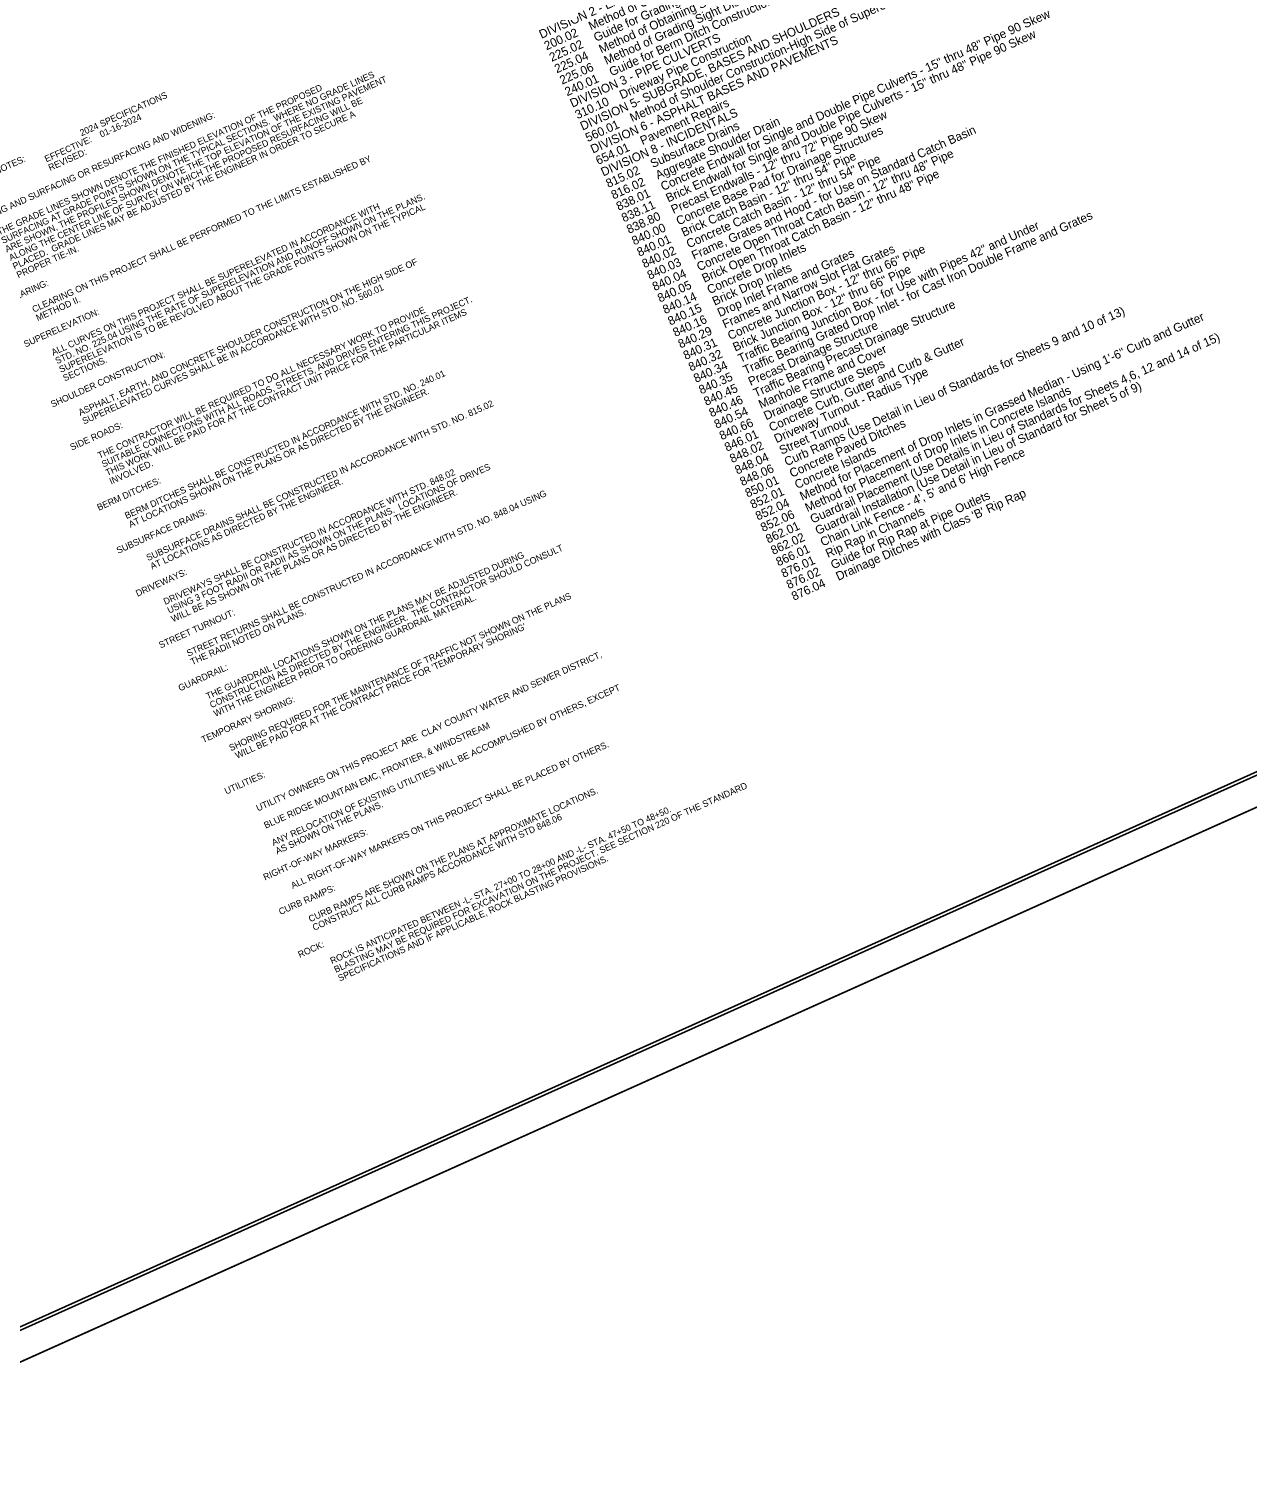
# Model space of a CAD drawing. Extents: x 553377 to 556641, y 502653 to 504402.
# Drawn here: x 554604 to 555547, y 502653 to 503778 of the extents above; entities that cross this region are included whole.
import ezdxf

# ---------------------------------------------------------------- set-up
doc = ezdxf.new("R2010")
doc.units = 0
for name, color, linetype in [('Prop Dimension Text', 7, 'Continuous'), ('Sheet Border Standard 30in CELL', 7, 'Continuous'), ('Sheet Cutting Line CELL', 7, 'Continuous'), ('Sheet Plot Border Inside CELL', 7, 'Continuous'), ('Sheet Plot Border Outside CELL', 7, 'Continuous')]:
    doc.layers.add(name, color=color, linetype=linetype)

msp = doc.modelspace()

# ---------------------------------------------------------------- linework, layer by layer
at = {"layer": 'Sheet Border Standard 30in CELL'}
msp.add_lwpolyline([(555469.6, 504316.8), (554101.2, 503702.4), (554531.3, 502744.5), (555899.7, 503359)], close=True, dxfattribs=at)
at = {"layer": 'Sheet Cutting Line CELL'}
msp.add_line((554389.2, 502653.3), (555925.5, 503343.1), dxfattribs=at)
at = {"layer": 'Sheet Plot Border Inside CELL'}
msp.add_lwpolyline([(555480, 504324.3), (553959.7, 503641.6), (554391.9, 502679.1), (555912.2, 503361.8)], close=True, dxfattribs=at)
at = {"layer": 'Sheet Plot Border Outside CELL'}
msp.add_lwpolyline([(555474.9, 504346.6), (553938.6, 503656.8), (554389.2, 502653.3), (555925.5, 503343.1)], close=True, dxfattribs=at)

# ---------------------------------------------------------------- texts
at = {"layer": 'Prop Dimension Text'}
for s, height, p in [('225.02    Guide for Grading Subgrade - Secondary and Local', 6.75, (555008.5, 503752.9)), ('225.04    Method of Obtaining Superelevation - Two Lane Pavement', 6.75, (555012.5, 503744)), ('200.02    Method of Clearing - Method II', 6.75, (555004.5, 503761.8)), ('225.06    Method of Grading Sight Distance at Intersections', 6.75, (555016.5, 503735.2)), ('560.01    Method of Shoulder Construction-High Side of Superelevated Curve-Method I', 6.75, (555036.4, 503690.8)), ('DIVISION 2 - EARTHWORK', 6.75, (555000.6, 503770.7)), ('240.01    Guide for Berm Ditch Construction', 6.75, (555020.5, 503726.3)), ('DIVISION 5- SUBGRADE, BASES AND SHOULDERS', 6.75, (555032.4, 503699.7)), ('838.01    Concrete Endwall for Single and Double Pipe Culverts - 15" thru 48" Pipe 90 Skew', 6.75, (555060.3, 503637.6)), ('DIVISION 3 - PIPE CULVERTS', 6.75, (555024.5, 503717.4)), ('838.11    Brick Endwall for Single and Double Pipe Culverts - 15" thru 48" Pipe 90 Skew', 6.75, (555064.3, 503628.7)), ('310.10    Driveway Pipe Construction', 6.75, (555028.4, 503708.5)), ('DIVISION 6 - ASPHALT BASES AND PAVEMENTS', 6.75, (555040.4, 503681.9)), ('         SURFACING AT GRADE POINTS SHOWN ON THE TYPICAL SECTIONS.  WHERE NO GRADE LINES ', 5.062, (554568.7, 503605.1)), ('         ARE SHOWN, THE PROFILES SHOWN DENOTE THE TOP ELEVATION OF THE EXISTING PAVEMENT ', 5.062, (554571.7, 503598.5)), ('GENERAL NOTES:                         2024 SPECIFICATIONS', 5.062, (554547.8, 503651.7)), ('         THE GRADE LINES SHOWN DENOTE THE FINISHED ELEVATION OF THE PROPOSED ', 5.062, (554565.7, 503611.8)), ('         ALONG THE CENTER LINE OF SURVEY ON WHICH THE PROPOSED RESURFACING WILL BE ', 5.062, (554574.7, 503591.8)), ('654.01    Pavement Repairs', 6.75, (555044.4, 503673.1)), ('GRADING AND SURFACING OR RESURFACING AND WIDENING:  ', 5.062, (554559.7, 503625.1)), ('         PLACED.  GRADE LINES MAY BE ADJUSTED BY THE ENGINEER IN ORDER TO SECURE A ', 5.062, (554577.6, 503585.2)), ('                                       EFFECTIVE:    01-16-2024', 5.062, (554550.8, 503645.1)), ('DIVISION 8 - INCIDENTALS', 6.75, (555048.4, 503664.2)), ('816.02    Aggregate Shoulder Drain', 6.75, (555056.3, 503646.4)), ('838.80    Precast Endwalls - 12" thru 72" Pipe 90 Skew', 6.75, (555068.3, 503619.8)), ('815.02    Subsurface Drains', 6.75, (555052.3, 503655.3)), ('840.00    Concrete Base Pad for Drainage Structures', 6.75, (555072.3, 503610.9)), ('840.03    Frame, Grates and Hood - for Use on Standard Catch Basin', 6.75, (555084.2, 503584.3)), ('                                       REVISED:      ', 5.062, (554553.7, 503638.4)), ('840.04    Concrete Open Throat Catch Basin - 12" thru 48" Pipe', 6.75, (555088.2, 503575.5)), ('         CLEARING ON THIS PROJECT SHALL BE PERFORMED TO THE LIMITS ESTABLISHED BY ', 5.062, (554592.6, 503551.9)), ('840.01    Brick Catch Basin - 12" thru 54" Pipe', 6.75, (555076.3, 503602.1)), ('840.02    Concrete Catch Basin - 12" thru 54" Pipe', 6.75, (555080.2, 503593.2)), ('840.05    Brick Open Throat Catch Basin - 12" thru 48" Pipe', 6.75, (555092.2, 503566.6)), ('         STD. NO. 225.04 USING THE RATE OF SUPERELEVATION AND RUNOFF SHOWN ON THE PLANS.', 5.062, (554610.5, 503512)), ('         ALL CURVES ON THIS PROJECT SHALL BE SUPERELEVATED IN ACCORDANCE WITH', 5.062, (554607.5, 503518.6)), ('         SUPERELEVATION IS TO BE REVOLVED ABOUT THE GRADE POINTS SHOWN ON THE TYPICAL ', 5.062, (554613.5, 503505.3)), ('840.34    Traffic Bearing Junction Box - for Use with Pipes 42" and Under', 6.75, (555120.1, 503504.5)), ('840.35    Traffic Bearing Grated Drop Inlet - for Cast Iron Double Frame and Grates', 6.75, (555124.1, 503495.6)), ('         PROPER TIE-IN.  ', 5.062, (554580.6, 503578.5)), ('840.14    Concrete Drop Inlets', 6.75, (555096.2, 503557.7)), ('840.16    Drop Inlet Frame and Grates', 6.75, (555104.1, 503540)), ('840.29    Frames and Narrow Slot Flat Grates', 6.75, (555108.1, 503531.1)), ('840.31    Concrete Junction Box - 12" thru 66" Pipe', 6.75, (555112.1, 503522.2)), ('         ASPHALT, EARTH, AND CONCRETE SHOULDER CONSTRUCTION ON THE HIGH SIDE OF', 5.062, (554628.4, 503472.1)), ('840.15    Brick Drop Inlets', 6.75, (555100.2, 503548.8)), ('840.32    Brick Junction Box - 12" thru 66" Pipe', 6.75, (555116.1, 503513.3)), ('CLEARING:  ', 5.062, (554586.6, 503565.2)), ('         SUPERELEVATED CURVES SHALL BE IN ACCORDANCE WITH STD. NO. 560.01', 5.062, (554631.4, 503465.4)), ('         SUITABLE CONNECTIONS WITH ALL ROADS, STREETS, AND DRIVES ENTERING THIS PROJECT.  ', 5.062, (554646.4, 503432.1)), ('SUPERELEVATION:  ', 5.062, (554601.6, 503531.9)), ('         METHOD II.', 5.062, (554595.6, 503545.3)), ('         THE CONTRACTOR WILL BE REQUIRED TO DO ALL NECESSARY WORK TO PROVIDE ', 5.062, (554643.4, 503438.8)), ('         THIS WORK WILL BE PAID FOR AT THE CONTRACT UNIT PRICE FOR THE PARTICULAR ITEMS ', 5.062, (554649.4, 503425.5)), ('840.46    Traffic Bearing Precast Drainage Structure', 6.75, (555132, 503477.8)), ('848.06    Curb Ramps (Use Detail in Lieu of Standards for Sheets 9 and 10 of 13)', 6.75, (555155.9, 503424.6)), ('840.45    Precast Drainage Structure', 6.75, (555128, 503486.7)), ('852.04    Method for Placement of Drop Inlets in Grassed Median - Using 1\'-6" Curb and Gutter', 6.75, (555167.9, 503398)), ('846.01    Concrete Curb, Gutter and Curb & Gutter', 6.75, (555144, 503451.2)), ('862.01    Guardrail Placement (Use Details in Lieu of Standards for Sheets 4,6, 12 and 14 of 15)', 6.75, (555175.9, 503380.2)), ('SHOULDER CONSTRUCTION:  ', 5.062, (554622.5, 503485.4)), ('840.54    Manhole Frame and Cover', 6.75, (555136, 503469)), ('         SECTIONS.  ', 5.062, (554616.5, 503498.7)), ('840.66    Drainage Structure Steps', 6.75, (555140, 503460.1)), ('848.02    Driveway Turnout - Radius Type', 6.75, (555148, 503442.4)), ('         BERM DITCHES SHALL BE CONSTRUCTED IN ACCORDANCE WITH STD. NO. 240.01 ', 5.062, (554664.3, 503392.2)), ('862.02    Guardrail Installation (Use Detail in Lieu of Standard for Sheet 5 of 9)', 6.75, (555179.8, 503371.4)), ('         AT LOCATIONS SHOWN ON THE PLANS OR AS DIRECTED BY THE ENGINEER.  ', 5.062, (554667.3, 503385.5)), ('852.06    Method for Placement of Drop Inlets in Concrete Islands', 6.75, (555171.9, 503389.1)), ('          SUBSURFACE DRAINS SHALL BE CONSTRUCTED IN ACCORDANCE WITH STD. NO. 815.02', 5.062, (554679.2, 503358.9)), ('SIDE ROADS:  ', 5.062, (554637.4, 503452.1)), ('848.04    Street Turnout', 6.75, (555152, 503433.5)), ('850.01    Concrete Paved Ditches', 6.75, (555159.9, 503415.7)), ('852.01    Concrete Islands', 6.75, (555163.9, 503406.9)), ("866.01    Chain Link Fence - 4', 5' and 6' High Fence", 6.75, (555183.8, 503362.5)), ('         INVOLVED.  ', 5.062, (554652.4, 503418.8)), ('         DRIVEWAYS SHALL BE CONSTRUCTED IN ACCORDANCE WITH STD. 848.02', 5.062, (554694.2, 503325.7)), ('         USING 3 FOOT RADII OR RADII AS SHOWN ON THE PLANS.  LOCATIONS OF DRIVES', 5.062, (554697.2, 503319)), ('BERM DITCHES:  ', 5.062, (554658.3, 503405.5)), ('          AT LOCATIONS AS DIRECTED BY THE ENGINEER.', 5.062, (554682.2, 503352.3)), ('         WILL BE AS SHOWN ON THE PLANS OR AS DIRECTED BY THE ENGINEER.  ', 5.062, (554700.2, 503312.3)), ('         STREET RETURNS SHALL BE CONSTRUCTED IN ACCORDANCE WITH STD. NO. 848.04 USING ', 5.062, (554712.1, 503285.7)), ('876.02    Guide for Rip Rap at Pipe Outlets', 6.75, (555191.8, 503344.8)), ("876.04    Drainage Ditches with Class 'B' Rip Rap", 6.75, (555195.8, 503335.9)), ('SUBSURFACE DRAINS:', 5.062, (554673.3, 503372.2)), ('876.01    Rip Rap in Channels', 6.75, (555187.8, 503353.6)), ('         THE GUARDRAIL LOCATIONS SHOWN ON THE PLANS MAY BE ADJUSTED DURING ', 5.062, (554727.1, 503252.5)), ('         CONSTRUCTION AS DIRECTED BY THE ENGINEER.  THE CONTRACTOR SHOULD CONSULT', 5.062, (554730, 503245.8)), ('DRIVEWAYS:  ', 5.062, (554688.2, 503339)), ('         WITH THE ENGINEER PRIOR TO ORDERING GUARDRAIL MATERIAL.', 5.062, (554733, 503239.1)), ('         SHORING REQUIRED FOR THE MAINTENANCE OF TRAFFIC NOT SHOWN ON THE PLANS', 5.062, (554745, 503212.5)), ('STREET TURNOUT:  ', 5.062, (554706.1, 503299)), ('         THE RADII NOTED ON PLANS.  ', 5.062, (554715.1, 503279.1)), ("          WILL BE PAID FOR AT THE CONTRACT PRICE FOR 'TEMPORARY SHORING'", 5.062, (554748, 503205.9)), ('         UTILITY OWNERS ON THIS PROJECT ARE  CLAY COUNTY WATER AND SEWER DISTRICT,', 5.062, (554765.9, 503165.9)), ('GUARDRAIL:  ', 5.062, (554721.1, 503265.8)), ('         ANY RELOCATION OF EXISTING UTILITIES WILL BE ACCOMPLISHED BY OTHERS, EXCEPT ', 5.062, (554777.9, 503139.3)), ('TEMPORARY SHORING:  ', 5.062, (554739, 503225.8)), ('         BLUE RIDGE MOUNTAIN EMC, FRONTIER, & WINDSTREAM', 5.062, (554771.9, 503152.6)), ('         ALL RIGHT-OF-WAY MARKERS ON THIS PROJECT SHALL BE PLACED BY OTHERS.', 5.062, (554792.8, 503106)), ('UTILITIES:  ', 5.062, (554756.9, 503185.9)), ('          CURB RAMPS ARE SHOWN ON THE PLANS AT APPROXIMATE LOCATIONS.', 5.062, (554804.7, 503079.4)), ('           BLASTING MAY BE REQUIRED FOR EXCAVATION ON THE PROJECT. SEE SECTION 220 OF THE STANDARD', 5.062, (554822.7, 503039.5)), ('         AS SHOWN ON THE PLANS.  ', 5.062, (554780.8, 503132.7)), ('          CONSTRUCT ALL CURB RAMPS ACCORDANCE WITH STD 848.06  ', 5.062, (554807.7, 503072.8)), ('           ROCK IS ANTICIPATED BETWEEN -L- STA. 27+00 TO 28+00 AND -L- STA. 47+50 TO 48+50.', 5.062, (554819.7, 503046.2)), ('RIGHT-OF-WAY MARKERS:  ', 5.062, (554786.8, 503119.4)), ('           SPECIFICATIONS AND IF APPLICABLE, ROCK BLASTING PROVISIONS.', 5.062, (554825.7, 503032.8)), ('CURB RAMPS:', 5.062, (554798.8, 503092.7)), ('ROCK:', 5.06, (554813.7, 503059.5))]:
    msp.add_text(s, height=height, rotation=24.1816, dxfattribs=at).set_placement(p)

doc.saveas('drawing.dxf')
